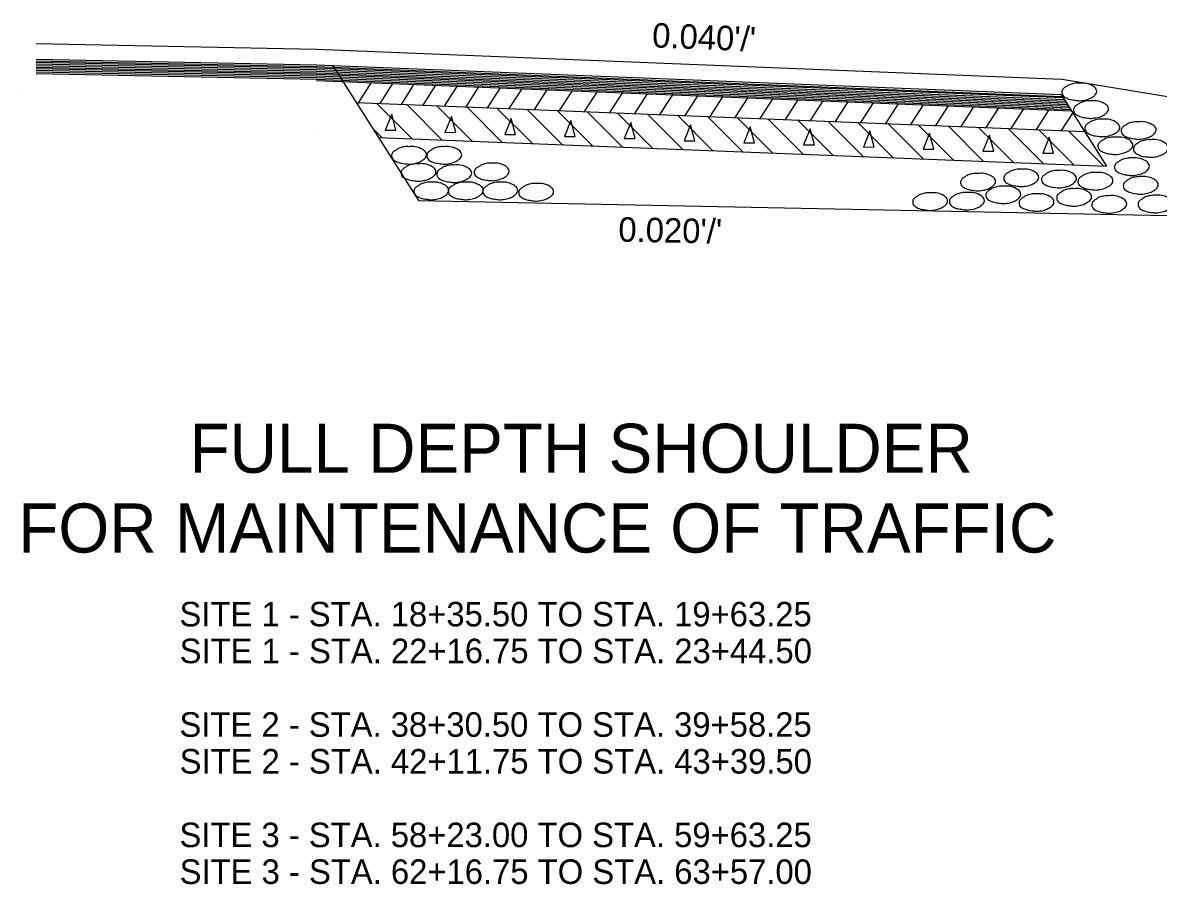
# Model space of a CAD drawing. Extents: x -2842 to 2681, y -2139 to 474.
# Drawn here: x -233.5 to 44.4, y -1194.5 to -983.8 of the extents above; entities that cross this region are included whole.
import ezdxf

# ---------------------------------------------------------------- set-up
doc = ezdxf.new("R2010")
doc.units = 0
doc.layers.add('Default', color=7, linetype='Continuous')

msp = doc.modelspace()

# ---------------------------------------------------------------- linework, layer by layer
at = {"layer": 'Default'}
for p, q in [((-230.22, -988.87), (-161.61, -990.24)), ((-161.61, -990.24), (20.78, -997.55)), ((-230.22, -992.69), (-161.61, -994.04)), ((-230.22, -993.11), (-161.61, -994.48)), ((-230.22, -993.43), (-161.61, -994.81)), ((-230.22, -993.84), (-161.61, -995.23)), ((-230.22, -994.24), (-161.61, -995.65)), ((-230.22, -994.62), (-161.61, -996.01)), ((-230.22, -995.01), (-161.61, -996.39)), ((-161.61, -994.04), (20.62, -1001.37)), ((-161.61, -994.48), (20.9, -1001.82)), ((-161.61, -994.81), (21.09, -1002.11)), ((-157.69, -994.19), (-136.65, -1027.3)), ((-230.22, -995.4), (-161.61, -996.77)), ((-230.22, -995.83), (-161.61, -997.19)), ((-230.22, -996.21), (-161.61, -997.56)), ((-161.61, -995.23), (21.4, -1002.57)), ((-161.61, -995.65), (21.62, -1002.97)), ((-161.61, -996.01), (21.9, -1003.41)), ((-161.61, -996.39), (22.12, -1003.75)), ((-161.61, -996.77), (22.44, -1004.19)), ((-161.61, -997.19), (22.68, -1004.59)), ((-161.61, -997.56), (22.94, -1005.03)), ((20.9, -997.55), (412.13, -1062.76)), ((-161.61, -997.89), (23.11, -1005.31)), ((-151.59, -1003.79), (-148.18, -998.4)), ((-146.06, -1003.55), (-142.94, -998.62)), ((-140.81, -1003.76), (-137.68, -998.82)), ((-135.52, -1003.97), (-132.4, -999.08)), ((-130.26, -1004.18), (-127.15, -999.25)), ((-124.98, -1004.38), (-121.89, -999.48)), ((-119.73, -1004.59), (-116.62, -999.67)), ((-114.43, -1004.8), (-111.27, -999.92)), ((-108.28, -1005.04), (-105.13, -1000.17)), ((-102.12, -1005.29), (-98.95, -1000.4)), ((-233.53, -1001.46), (-233.53, -1001.46)), ((-151.89, -1003.32), (26.33, -1010.36)), ((-96, -1005.53), (-92.84, -1000.63)), ((-89.81, -1005.77), (-86.67, -1000.88)), ((-83.71, -1006.01), (-80.58, -1001.15)), ((-77.55, -1006.26), (-74.42, -1001.38)), ((-71.4, -1006.5), (-68.28, -1001.65)), ((-65.29, -1006.74), (-62.14, -1001.88)), ((-59.11, -1006.98), (-55.97, -1002.1)), ((-53, -1007.23), (-49.88, -1002.35)), ((-46.83, -1007.47), (-43.71, -1002.63)), ((-40.71, -1007.71), (-37.57, -1002.88)), ((-34.58, -1007.95), (-31.46, -1003.11)), ((-28.41, -1008.2), (-25.32, -1003.38)), ((20.62, -1001.37), (31.75, -1018.89)), ((-138.23, -1012.18), (-146.89, -1003.52)), ((-130.87, -1012.47), (-139.53, -1003.81)), ((-123.51, -1012.76), (-132.17, -1004.1)), ((-116.15, -1013.05), (-124.81, -1004.39)), ((-108.79, -1013.34), (-117.45, -1004.68)), ((-101.42, -1013.63), (-110.09, -1004.97)), ((-94.06, -1013.92), (-102.72, -1005.26)), ((-86.7, -1014.22), (-95.36, -1005.55)), ((-79.34, -1014.51), (-88, -1005.84)), ((-71.98, -1014.8), (-80.64, -1006.13)), ((-22.31, -1008.44), (-19.19, -1003.59)), ((-16.14, -1008.68), (-13.05, -1003.84)), ((-10.01, -1008.92), (-6.91, -1004.11)), ((-3.84, -1009.17), (-0.73, -1004.34)), ((2.29, -1009.41), (5.4, -1004.59)), ((8.43, -1009.65), (11.54, -1004.83)), ((14.58, -1009.89), (17.69, -1005.07)), ((20.74, -1010.14), (23.47, -1005.87)), ((-64.62, -1015.09), (-73.28, -1006.43)), ((-57.25, -1015.38), (-65.92, -1006.72)), ((-49.89, -1015.67), (-58.55, -1007.01)), ((-42.53, -1015.96), (-51.19, -1007.3)), ((-35.17, -1016.25), (-43.83, -1007.59)), ((-27.81, -1016.54), (-36.47, -1007.88)), ((-20.45, -1016.83), (-29.11, -1008.17)), ((-13.08, -1017.12), (-21.75, -1008.46)), ((-5.72, -1017.41), (-14.38, -1008.75)), ((-161.81, -1011.25), (-161.81, -1011.25)), ((-145.59, -1011.89), (-147.92, -1009.56)), ((1.64, -1017.7), (-7.02, -1009.04)), ((9, -1017.99), (0.34, -1009.33)), ((16.36, -1018.28), (7.7, -1009.62)), ((23.72, -1018.57), (15.06, -1009.91)), ((31.09, -1018.87), (22.42, -1010.2)), ((-146.46, -1011.86), (31.75, -1018.89)), ((-136.65, -1027.3), (245.22, -1034.95))]:
    msp.add_line(p, q, dxfattribs=at)
for points in [[(-143.22, -1006.17), (-144.82, -1010.1), (-142.17, -1010.08), (-143.22, -1006.17)], [(-128.59, -1006.68), (-130.18, -1010.61), (-127.54, -1010.59), (-128.59, -1006.68)], [(-113.96, -1007.19), (-115.55, -1011.12), (-112.91, -1011.1), (-113.96, -1007.19)], [(-99.33, -1007.7), (-100.92, -1011.63), (-98.28, -1011.62), (-99.33, -1007.7)], [(-84.7, -1008.21), (-86.29, -1012.14), (-83.65, -1012.13), (-84.7, -1008.21)], [(-70.07, -1008.72), (-71.66, -1012.65), (-69.02, -1012.64), (-70.07, -1008.72)], [(-55.44, -1009.23), (-57.03, -1013.16), (-54.39, -1013.15), (-55.44, -1009.23)], [(-40.81, -1009.74), (-42.4, -1013.67), (-39.76, -1013.66), (-40.81, -1009.74)], [(-26.18, -1010.25), (-27.77, -1014.19), (-25.12, -1014.17), (-26.18, -1010.25)], [(-11.55, -1010.77), (-13.14, -1014.7), (-10.49, -1014.68), (-11.55, -1010.77)], [(3.09, -1011.28), (1.5, -1015.21), (4.14, -1015.19), (3.09, -1011.28)], [(17.72, -1011.79), (16.13, -1015.72), (18.77, -1015.7), (17.72, -1011.79)]]:
    msp.add_lwpolyline(points, dxfattribs=at)
for points in [[(25, -998.58), (26.53, -998.59), (28.35, -999.23), (29.24, -1000.06), (29.36, -1000.6), (28.9, -1001.52), (28.38, -1001.91), (27.38, -1002.43), (25.92, -1002.77), (25.16, -1002.85), (24.05, -1002.74), (22.79, -1002.53), (21.84, -1002.16), (20.96, -1001.43), (20.81, -1000.85), (21.07, -1000.03), (21.77, -999.5), (22.41, -999.08), (23.43, -998.73), (24.06, -998.59), (25, -998.58)], [(27.88, -1002.91), (29.38, -1002.92), (31.2, -1003.56), (32.12, -1004.4), (32.25, -1004.93), (31.76, -1005.85), (31.22, -1006.27), (30.27, -1006.77), (28.75, -1007.08), (28.02, -1007.19), (26.88, -1007.07), (25.67, -1006.87), (24.73, -1006.48), (23.83, -1005.79), (23.67, -1005.18), (23.96, -1004.37), (24.64, -1003.81), (25.3, -1003.39), (26.28, -1003.08), (26.9, -1002.92), (27.88, -1002.91)], [(30.64, -1007.38), (32.15, -1007.4), (33.96, -1008.02), (34.86, -1008.89), (35.02, -1009.39), (34.54, -1010.33), (34.01, -1010.75), (33.02, -1011.2), (31.54, -1011.59), (30.78, -1011.65), (29.66, -1011.57), (28.43, -1011.35), (27.48, -1010.97), (26.6, -1010.26), (26.45, -1009.66), (26.71, -1008.86), (27.4, -1008.28), (28.04, -1007.85), (29.07, -1007.54), (29.69, -1007.4), (30.64, -1007.38)], [(39.54, -1008), (41.05, -1008.02), (42.86, -1008.64), (43.78, -1009.52), (43.89, -1010), (43.43, -1010.95), (42.9, -1011.35), (41.92, -1011.84), (40.43, -1012.21), (39.68, -1012.27), (38.56, -1012.16), (37.33, -1011.96), (36.36, -1011.59), (35.49, -1010.86), (35.33, -1010.28), (35.6, -1009.47), (36.3, -1008.91), (36.94, -1008.49), (37.96, -1008.16), (38.57, -1008.02), (39.54, -1008)], [(33.85, -1011.76), (35.33, -1011.78), (37.17, -1012.37), (38.04, -1013.24), (38.2, -1013.74), (37.73, -1014.69), (37.19, -1015.09), (36.2, -1015.56), (34.74, -1015.94), (33.96, -1016), (32.85, -1015.92), (31.62, -1015.72), (30.67, -1015.31), (29.77, -1014.6), (29.64, -1014.03), (29.91, -1013.21), (30.59, -1012.66), (31.22, -1012.23), (32.25, -1011.88), (32.87, -1011.78), (33.85, -1011.76)], [(-139.05, -1014.1), (-137.52, -1014.11), (-135.7, -1014.75), (-134.81, -1015.58), (-134.69, -1016.12), (-135.15, -1017.04), (-135.67, -1017.43), (-136.67, -1017.95), (-138.13, -1018.29), (-138.89, -1018.37), (-140, -1018.26), (-141.26, -1018.05), (-142.21, -1017.68), (-143.09, -1016.95), (-143.24, -1016.37), (-142.98, -1015.55), (-142.28, -1015.02), (-141.64, -1014.6), (-140.62, -1014.25), (-139.99, -1014.11), (-139.05, -1014.1)], [(-130.44, -1014.1), (-128.91, -1014.11), (-127.09, -1014.75), (-126.2, -1015.58), (-126.08, -1016.12), (-126.54, -1017.04), (-127.06, -1017.43), (-128.06, -1017.95), (-129.52, -1018.29), (-130.28, -1018.37), (-131.39, -1018.26), (-132.65, -1018.05), (-133.6, -1017.68), (-134.48, -1016.95), (-134.63, -1016.37), (-134.37, -1015.55), (-133.67, -1015.02), (-133.03, -1014.6), (-132.01, -1014.25), (-131.38, -1014.11), (-130.44, -1014.1)], [(42.56, -1012.4), (44.04, -1012.41), (45.88, -1013.04), (46.75, -1013.91), (46.91, -1014.41), (46.44, -1015.34), (45.9, -1015.75), (44.91, -1016.23), (43.45, -1016.61), (42.67, -1016.65), (41.58, -1016.59), (40.33, -1016.39), (39.38, -1015.98), (38.49, -1015.28), (38.35, -1014.69), (38.63, -1013.86), (39.32, -1013.3), (39.93, -1012.87), (40.96, -1012.57), (41.6, -1012.41), (42.56, -1012.4)], [(37.87, -1016.86), (39.41, -1016.9), (41.24, -1017.51), (42.13, -1018.38), (42.23, -1018.88), (41.77, -1019.83), (41.25, -1020.24), (40.27, -1020.72), (38.79, -1021.08), (38.03, -1021.14), (36.92, -1021.05), (35.7, -1020.83), (34.74, -1020.46), (33.85, -1019.75), (33.69, -1019.15), (33.96, -1018.32), (34.65, -1017.79), (35.3, -1017.35), (36.3, -1017.03), (36.94, -1016.9), (37.87, -1016.86)], [(-136.74, -1018.28), (-135.21, -1018.29), (-133.39, -1018.93), (-132.5, -1019.76), (-132.38, -1020.3), (-132.84, -1021.22), (-133.36, -1021.61), (-134.36, -1022.13), (-135.82, -1022.47), (-136.58, -1022.55), (-137.69, -1022.44), (-138.95, -1022.23), (-139.9, -1021.86), (-140.78, -1021.13), (-140.93, -1020.55), (-140.67, -1019.73), (-139.97, -1019.2), (-139.33, -1018.78), (-138.31, -1018.43), (-137.68, -1018.29), (-136.74, -1018.28)], [(-127.99, -1018.59), (-126.46, -1018.6), (-124.64, -1019.24), (-123.75, -1020.07), (-123.63, -1020.61), (-124.09, -1021.53), (-124.61, -1021.92), (-125.61, -1022.44), (-127.07, -1022.78), (-127.83, -1022.86), (-128.94, -1022.75), (-130.2, -1022.54), (-131.15, -1022.17), (-132.03, -1021.44), (-132.18, -1020.86), (-131.92, -1020.04), (-131.22, -1019.51), (-130.58, -1019.09), (-129.56, -1018.74), (-128.93, -1018.6), (-127.99, -1018.59)], [(-118.83, -1018.15), (-117.3, -1018.16), (-115.48, -1018.8), (-114.59, -1019.63), (-114.47, -1020.17), (-114.93, -1021.09), (-115.45, -1021.48), (-116.45, -1022), (-117.91, -1022.34), (-118.67, -1022.42), (-119.78, -1022.31), (-121.04, -1022.1), (-121.99, -1021.73), (-122.87, -1021), (-123.02, -1020.42), (-122.76, -1019.6), (-122.06, -1019.07), (-121.42, -1018.65), (-120.4, -1018.3), (-119.77, -1018.16), (-118.83, -1018.15)], [(10.8, -1019.6), (12.33, -1019.61), (14.15, -1020.25), (15.04, -1021.08), (15.16, -1021.62), (14.7, -1022.54), (14.18, -1022.93), (13.18, -1023.45), (11.72, -1023.79), (10.96, -1023.87), (9.85, -1023.76), (8.59, -1023.55), (7.64, -1023.18), (6.76, -1022.45), (6.61, -1021.87), (6.87, -1021.05), (7.57, -1020.52), (8.21, -1020.1), (9.23, -1019.75), (9.86, -1019.61), (10.8, -1019.6)], [(20.03, -1019.91), (21.56, -1019.92), (23.38, -1020.56), (24.27, -1021.39), (24.39, -1021.93), (23.93, -1022.85), (23.41, -1023.24), (22.41, -1023.76), (20.95, -1024.1), (20.19, -1024.18), (19.08, -1024.07), (17.82, -1023.86), (16.87, -1023.49), (15.99, -1022.76), (15.84, -1022.18), (16.1, -1021.36), (16.8, -1020.83), (17.44, -1020.41), (18.46, -1020.06), (19.09, -1019.92), (20.03, -1019.91)], [(-133.61, -1022.81), (-132.08, -1022.82), (-130.26, -1023.46), (-129.37, -1024.29), (-129.25, -1024.83), (-129.71, -1025.75), (-130.23, -1026.14), (-131.23, -1026.66), (-132.69, -1027), (-133.45, -1027.08), (-134.56, -1026.97), (-135.82, -1026.76), (-136.77, -1026.39), (-137.65, -1025.66), (-137.8, -1025.08), (-137.54, -1024.26), (-136.84, -1023.73), (-136.2, -1023.31), (-135.18, -1022.96), (-134.55, -1022.82), (-133.61, -1022.81)], [(-125.18, -1022.81), (-123.65, -1022.82), (-121.83, -1023.46), (-120.94, -1024.29), (-120.82, -1024.83), (-121.28, -1025.75), (-121.8, -1026.14), (-122.8, -1026.66), (-124.26, -1027), (-125.02, -1027.08), (-126.13, -1026.97), (-127.39, -1026.76), (-128.34, -1026.39), (-129.22, -1025.66), (-129.37, -1025.08), (-129.11, -1024.26), (-128.41, -1023.73), (-127.77, -1023.31), (-126.75, -1022.96), (-126.12, -1022.82), (-125.18, -1022.81)], [(-116.74, -1022.81), (-115.21, -1022.82), (-113.39, -1023.46), (-112.5, -1024.29), (-112.38, -1024.83), (-112.84, -1025.75), (-113.36, -1026.14), (-114.36, -1026.66), (-115.82, -1027), (-116.58, -1027.08), (-117.69, -1026.97), (-118.95, -1026.76), (-119.9, -1026.39), (-120.78, -1025.66), (-120.93, -1025.08), (-120.67, -1024.26), (-119.97, -1023.73), (-119.33, -1023.31), (-118.31, -1022.96), (-117.68, -1022.82), (-116.74, -1022.81)], [(0.22, -1020.64), (1.75, -1020.65), (3.57, -1021.29), (4.46, -1022.12), (4.58, -1022.66), (4.12, -1023.58), (3.6, -1023.97), (2.6, -1024.49), (1.14, -1024.83), (0.38, -1024.91), (-0.73, -1024.8), (-1.99, -1024.59), (-2.94, -1024.22), (-3.82, -1023.49), (-3.97, -1022.91), (-3.71, -1022.09), (-3.01, -1021.56), (-2.37, -1021.14), (-1.35, -1020.79), (-0.72, -1020.65), (0.22, -1020.64)], [(28.95, -1020.43), (30.48, -1020.44), (32.3, -1021.08), (33.19, -1021.91), (33.31, -1022.45), (32.85, -1023.37), (32.33, -1023.76), (31.33, -1024.28), (29.87, -1024.62), (29.11, -1024.7), (28, -1024.59), (26.74, -1024.38), (25.79, -1024.01), (24.91, -1023.28), (24.76, -1022.7), (25.02, -1021.88), (25.72, -1021.35), (26.36, -1020.93), (27.38, -1020.58), (28.01, -1020.44), (28.95, -1020.43)], [(40.04, -1021.42), (41.58, -1021.47), (43.4, -1022.08), (44.29, -1022.95), (44.4, -1023.45), (43.93, -1024.4), (43.42, -1024.8), (42.44, -1025.29), (40.96, -1025.64), (40.19, -1025.71), (39.09, -1025.61), (37.87, -1025.39), (36.9, -1025.02), (36.02, -1024.32), (35.86, -1023.71), (36.13, -1022.89), (36.81, -1022.36), (37.47, -1021.92), (38.46, -1021.59), (39.1, -1021.47), (40.04, -1021.42)], [(-107.94, -1023.13), (-106.41, -1023.14), (-104.59, -1023.78), (-103.7, -1024.61), (-103.58, -1025.15), (-104.04, -1026.07), (-104.56, -1026.46), (-105.56, -1026.98), (-107.02, -1027.32), (-107.78, -1027.4), (-108.89, -1027.29), (-110.15, -1027.08), (-111.1, -1026.71), (-111.98, -1025.98), (-112.13, -1025.4), (-111.87, -1024.58), (-111.17, -1024.05), (-110.53, -1023.63), (-109.51, -1023.28), (-108.88, -1023.14), (-107.94, -1023.13)], [(-11.5, -1025.41), (-9.97, -1025.42), (-8.15, -1026.06), (-7.26, -1026.89), (-7.14, -1027.43), (-7.6, -1028.35), (-8.12, -1028.74), (-9.12, -1029.26), (-10.58, -1029.6), (-11.34, -1029.68), (-12.45, -1029.57), (-13.71, -1029.36), (-14.66, -1028.99), (-15.54, -1028.26), (-15.69, -1027.68), (-15.43, -1026.86), (-14.73, -1026.33), (-14.09, -1025.91), (-13.07, -1025.56), (-12.44, -1025.42), (-11.5, -1025.41)], [(-2.52, -1025.31), (-0.99, -1025.32), (0.83, -1025.96), (1.72, -1026.79), (1.84, -1027.33), (1.38, -1028.25), (0.86, -1028.64), (-0.14, -1029.16), (-1.6, -1029.5), (-2.36, -1029.58), (-3.47, -1029.47), (-4.73, -1029.26), (-5.68, -1028.89), (-6.56, -1028.16), (-6.71, -1027.58), (-6.45, -1026.76), (-5.75, -1026.23), (-5.11, -1025.81), (-4.09, -1025.46), (-3.46, -1025.32), (-2.52, -1025.31)], [(6.39, -1023.75), (7.92, -1023.76), (9.74, -1024.4), (10.63, -1025.23), (10.75, -1025.77), (10.29, -1026.69), (9.77, -1027.08), (8.77, -1027.6), (7.31, -1027.94), (6.55, -1028.02), (5.44, -1027.91), (4.18, -1027.7), (3.23, -1027.33), (2.35, -1026.6), (2.2, -1026.02), (2.46, -1025.2), (3.16, -1024.67), (3.8, -1024.25), (4.82, -1023.9), (5.45, -1023.76), (6.39, -1023.75)], [(14.52, -1025.63), (16.05, -1025.64), (17.87, -1026.28), (18.76, -1027.11), (18.88, -1027.65), (18.42, -1028.57), (17.9, -1028.96), (16.9, -1029.48), (15.44, -1029.82), (14.68, -1029.9), (13.57, -1029.79), (12.31, -1029.58), (11.36, -1029.21), (10.48, -1028.48), (10.33, -1027.9), (10.59, -1027.08), (11.29, -1026.55), (11.93, -1026.13), (12.95, -1025.78), (13.58, -1025.64), (14.52, -1025.63)], [(23.74, -1024.38), (25.27, -1024.39), (27.09, -1025.03), (27.98, -1025.86), (28.1, -1026.4), (27.64, -1027.32), (27.12, -1027.71), (26.12, -1028.23), (24.66, -1028.57), (23.9, -1028.65), (22.79, -1028.54), (21.53, -1028.33), (20.58, -1027.96), (19.7, -1027.23), (19.55, -1026.65), (19.81, -1025.83), (20.51, -1025.3), (21.15, -1024.88), (22.17, -1024.53), (22.8, -1024.39), (23.74, -1024.38)], [(32.33, -1026.1), (33.86, -1026.11), (35.68, -1026.75), (36.57, -1027.58), (36.69, -1028.12), (36.23, -1029.04), (35.71, -1029.43), (34.71, -1029.95), (33.25, -1030.29), (32.49, -1030.37), (31.38, -1030.26), (30.12, -1030.05), (29.17, -1029.68), (28.29, -1028.95), (28.14, -1028.37), (28.4, -1027.55), (29.1, -1027.02), (29.74, -1026.6), (30.76, -1026.25), (31.39, -1026.11), (32.33, -1026.1)], [(43.64, -1025.99), (45.18, -1026.03), (47, -1026.64), (47.89, -1027.51), (48, -1028.01), (47.53, -1028.96), (47.02, -1029.37), (46.04, -1029.85), (44.56, -1030.21), (43.79, -1030.27), (42.69, -1030.18), (41.47, -1029.96), (40.5, -1029.59), (39.62, -1028.89), (39.46, -1028.28), (39.73, -1027.45), (40.41, -1026.92), (41.07, -1026.49), (42.06, -1026.16), (42.7, -1026.03), (43.64, -1025.99)]]:
    msp.add_spline(points, degree=3, dxfattribs=at)

# ---------------------------------------------------------------- texts
for s, rotation, p in [("0.040'/'", 357.7077, (-79.55, -989.81)), ("0.020'/'", 358.8543, (-87.78, -1037.32))]:
    msp.add_text(s, height=6, rotation=rotation, dxfattribs=at).set_placement(p)
for s, height, p in [('FULL DEPTH SHOULDER', 12, (-192.68, -1093.88)), ('FOR MAINTENANCE OF TRAFFIC', 12, (-234.62, -1113.38)), ('SITE 1 - STA. 18+35.50 TO STA. 19+63.25', 6, (-195.16, -1131.45)), ('SITE 1 - STA. 22+16.75 TO STA. 23+44.50', 6, (-195.12, -1140.45)), ('SITE 2 - STA. 38+30.50 TO STA. 39+58.25', 6, (-195.17, -1158.45)), ('SITE 2 - STA. 42+11.75 TO STA. 43+39.50', 6, (-195.12, -1167.45)), ('SITE 3 - STA. 58+23.00 TO STA. 59+63.25', 6, (-195.16, -1185.45)), ('SITE 3 - STA. 62+16.75 TO STA. 63+57.00', 6, (-195.12, -1194.45))]:
    msp.add_text(s, height=height, dxfattribs=at).set_placement(p)

doc.saveas('drawing.dxf')
